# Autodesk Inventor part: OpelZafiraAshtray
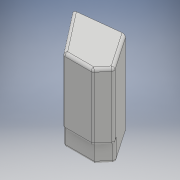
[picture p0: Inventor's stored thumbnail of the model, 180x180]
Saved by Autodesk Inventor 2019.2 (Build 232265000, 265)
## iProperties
Created: 2018-03
Part Number: OpelZafiraAshtray
Material: Genérico
Document SubType Name: Modeling
Designer: jose
Density: 1 g/cm^3
Appearance: Valor por defecto
Author: jose
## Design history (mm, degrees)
sketch "Boceto1"
  geometry: L1 (-65.696, 44.683)-(-31, 0); L2 (-31, 0)-(0, 0); L3 (0, 0)-(11.002, 12.959); L4 (11.002, 12.959)-(-14.611, 50.5); L5 (-14.611, 50.5)-(-65.696, 44.683); L6 (-14.611, 50.5)-(-50.957, 25.702); L7 (-31, 0)-(3.694, 23.671); L8 (18.795, 22.138)-(-14.611, 50.5); L9 (-65.696, 44.683)-(-5.473, -6.446); L10 (-14.611, 50.5)-(-14.611, 0); 1 further point
  constraints: 20 end point, 5 perpendicular, 5 point on line, 1 coincident, 1 horizontal
  dimensions: "d3" = 17 distance of L2.end L3.end; "d4" = 31 distance of L1.end L2.end; "d6" = 83 distance of L3.end L1.start; "d66" = 42 distance of L1.end L7.end; "d67" = 44 distance of L4.end L6.end; "d69" = 79 distance of L1.start L9.end; "d70" = 50.5 distance of L4.end L10.end
extrude "Extrusión1" new body sketch "Boceto1" distance "d7" = 92; taper "d8" = 0 deg
sketch "Boceto3"
  geometry: L1 (65.696, 44.683)-(31, 0) reference; L2 (14.611, 50.5)-(65.696, 44.683) reference; L3 (-11.002, 12.959)-(14.611, 50.5) reference; L4 (0, 0)-(-11.002, 12.959) reference; L5 (31, 0)-(0, 0) reference; L6 (-11.002, 12.959)-(-8.665, 16.386); L7 (-11.002, 12.959)-(14.611, 50.5) reference; L8 (1.851, 4)-(34.106, 4); L9 (65.696, 44.683)-(31, 0) reference; L10 (31, 0)-(1, 0); L11 (0, 0)-(-11.002, 12.959) reference; L12 (-11.002, 12.959)-(0, 0); L13 (1.851, 4)-(-8.665, 16.386); L14 (31, 0)-(0, 0) reference; L15 (31, 0)-(0, 0) reference; L16 (34.106, 4)-(31, 0)
  constraints: 12 end point, 2 collinear, 2 parallel, 2 point on line
  dimensions: "d18" = 4 distance between parallel lines of L5 L8; "d19" = 4 distance between parallel lines of L11 L13
extrude "Extrusión3" cut sketch "Boceto3" distance "d20" = 20; taper "d21" = 0 deg
fillet "Empalme2" dims "d71" = 3
feature "Vaciado3" dims "d72" = 1.5
node "Plano de trabajo1"
fillet "Empalme3" dims "d109" = 2
node "Sólido1"
node "Contorno proyectado2"
other parameters: "d89" = 90 deg
